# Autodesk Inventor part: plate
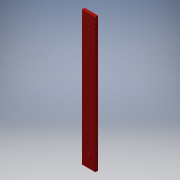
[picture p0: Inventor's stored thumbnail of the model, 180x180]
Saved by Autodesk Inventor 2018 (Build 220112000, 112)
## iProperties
Created: 2023-12
Part Number: plate
Material: Generic
Document SubType Name: Modeling
Designer: DDUGKY
Density: 1 g/cm^3
Appearance: Default
Author: DDUGKY
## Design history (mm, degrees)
sketch "Sketch1"
  geometry: L1 (25, 250)-(-25, 250); L2 (-25, 250)-(-25, -250); L3 (-25, -250)-(25, -250); L4 (25, -250)-(25, 250); L5 (25, 250)-(-25, -250); L6 (-25, 250)-(25, -250); C1 r 3.75 at (0, 200); C2 r 3.75 at (0, -200); 1 further point
  constraints: 12 end point, 2 centre point, 2 midpoint, 2 parallel, 1 horizontal, 1 perpendicular
  dimensions: "d0" = 50 distance of L3.end L2.end; "d1" = 500 distance of L2.end L1.end; "d6" = 7.5 diameter of C1; "d7" = 7.5 diameter of C2
extrude "Extrusion2" new body sketch "Sketch1" distance "d8" = 10; taper "d9" = 0 deg
body "Solid2"
